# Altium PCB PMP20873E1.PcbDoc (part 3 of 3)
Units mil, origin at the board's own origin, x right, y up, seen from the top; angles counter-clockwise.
Board outline 7700 x 3300 mil, 6 copper layers (Layer 1 - Top Layer, Layer 2 - Inner Signal 1, Layer 3 - Inner Signal 2, Layer 4 - Inner Signal 3, Layer 5 - Inner Signal 4, Layer 6 - Bottom Layer), stack 64 mil thick; 258 components, 121 nets, 676 pads, 168 vias.
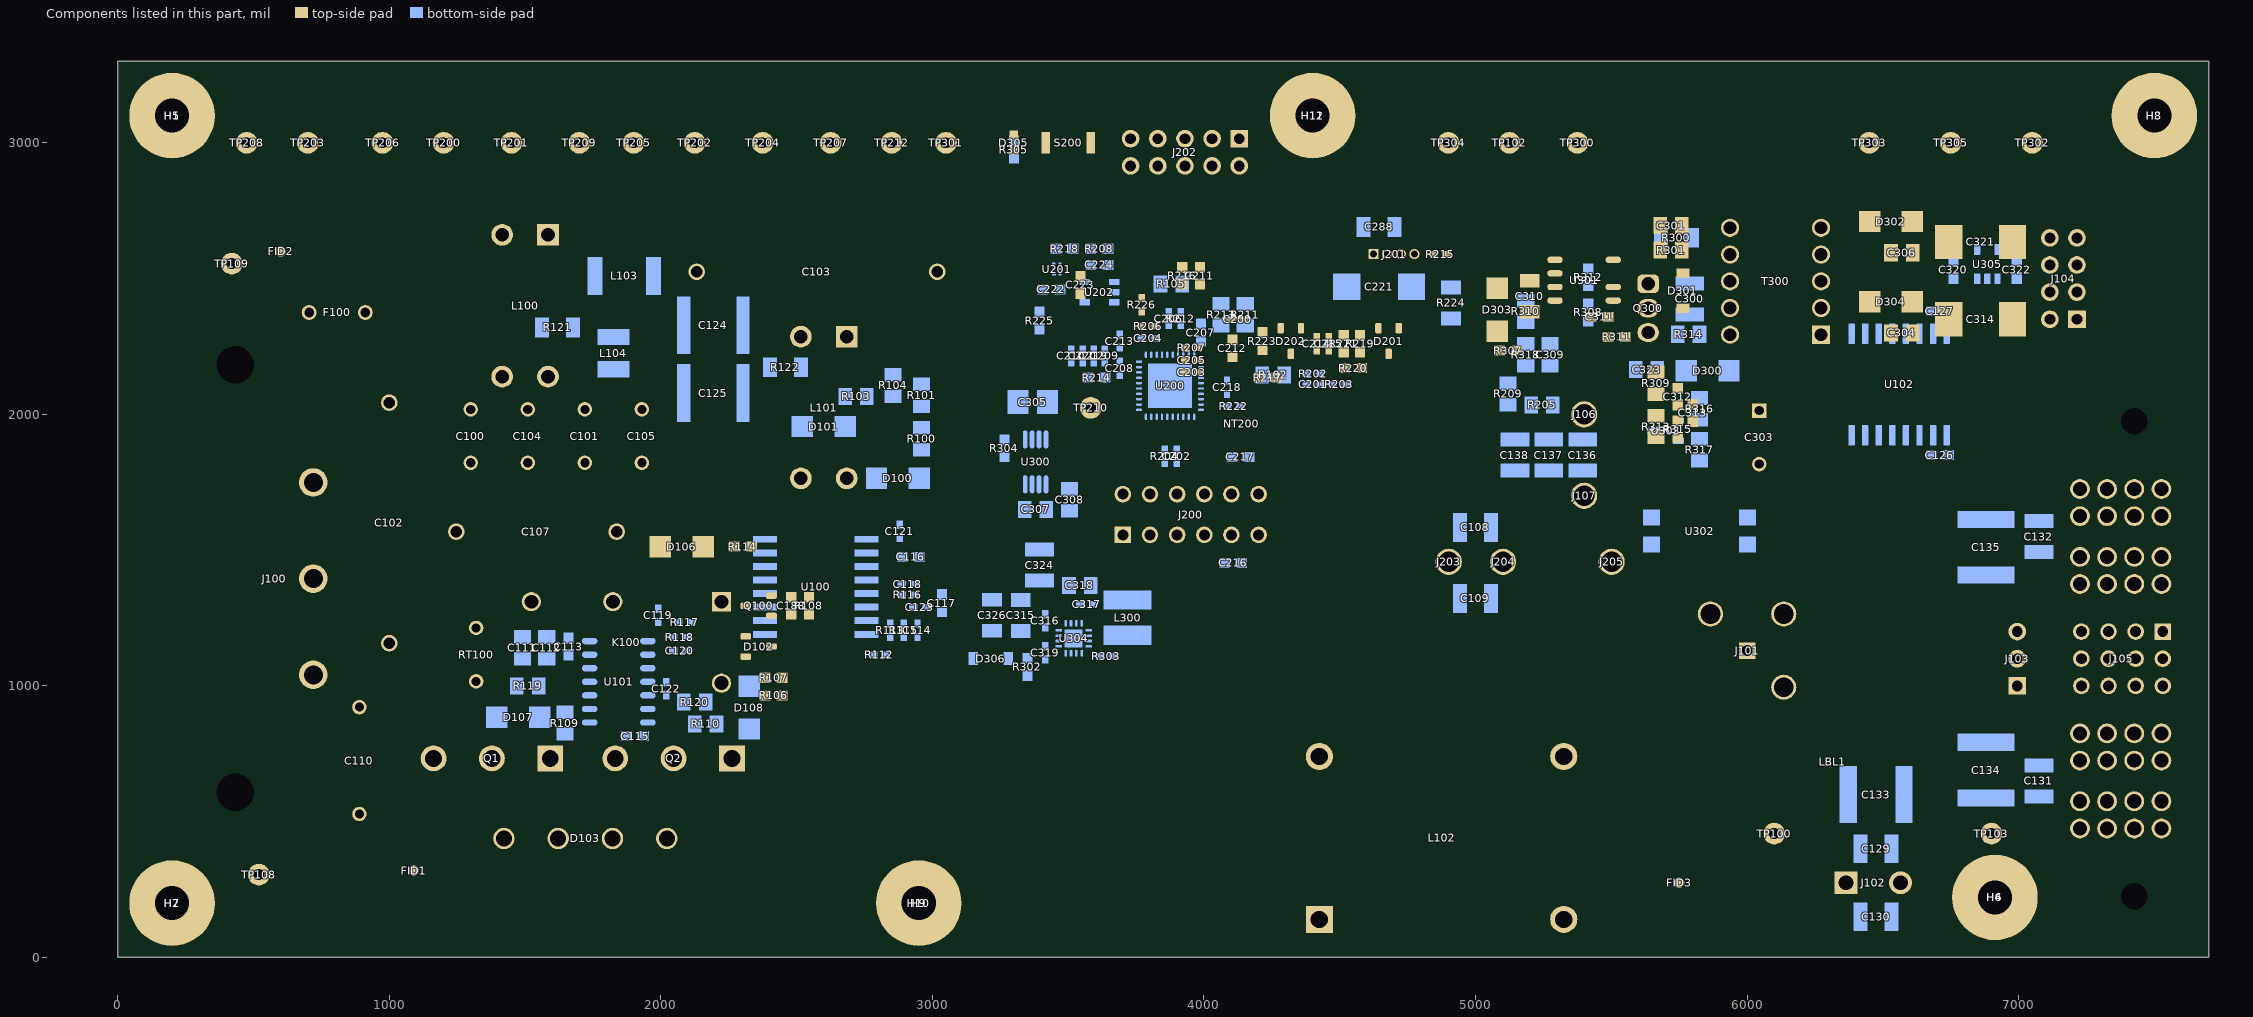
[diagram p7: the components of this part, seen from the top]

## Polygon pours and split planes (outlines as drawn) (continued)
5V on Layer 6 - Bottom Layer "5V_L06_P184" (solid, remove dead copper, pour order 184): 3310,1730 3310,1539 3419,1430 3539,1430 3546.48,1422.52 3545,1349 3574,1320 3574,1280 4100,1280 4100,1360 4100,1742.13 3950,1742.13 3950,1390 3930,1370 3680,1370 3660,1390 3660,1560 3550,1670 3440,1670 3360,1750 3330,1750
PGND_PFC on Layer 6 - Bottom Layer "PGND_PFC_L06_P182" (solid, remove dead copper, pour order 182): 3330,1115 3330,1010 3562,1010 3562,1131 3554,1139 3554,1208 3562,1216 3562,1313 3530,1345 3530,1418 3457,1418 3180,1418 3180,1245 3485,1245 3485,1135 3465,1115
12V on Layer 6 - Bottom Layer "12V_L06_P180" (solid, remove dead copper, pour order 180): 3455,1135 3230,1135 3184,1181 3184,1235 3435,1235 3445,1245 3495,1245 3495,1175
LLC_AGND on Layer 6 - Bottom Layer "Layer 6 - Bottom Layer-No Net 29" (solid, remove dead copper, pour order 103): 6235,2335 6400,2335 6400,2255 6235,2255
3V3 on Layer 6 - Bottom Layer "Layer 6 - Bottom Layer-No Net 27" (solid, remove dead copper, pour order 141): 3465,2570 3605,2570 3605,2475 3565,2435 3450,2435 3450,2555 3465,2570
NetC100_1 on Layer 6 - Bottom Layer "Layer 6 - Bottom Layer-No Net 26" (solid, remove dead copper, pour order 136): 1370,2095 1370,2219 1370,2375 1510,2515 1666,2515 1731,2580 1790,2580 1790,2435 1610,2435 1590,2415 1590,2280 1570,2260 1485,2175 1485,2095
NetL104_1 on Layer 6 - Bottom Layer "Layer 6 - Bottom Layer-No Net 25" (solid, remove dead copper, pour order 133): 1650,2360 1650,2270 1663,2257 1884,2257 1890,2263 1890,2335 1850,2375 1665,2375
NetC124_2 on Layer 6 - Bottom Layer "Layer 6 - Bottom Layer-No Net 24" (solid, remove dead copper, pour order 129): 2273.41,2438.41 2273.41,1968.41 2338.41,1968.41 2428.41,2058.41 2428.41,2215 2385,2215 2333.41,2266.59 2333.41,2438.41
NetC124_1 on Layer 6 - Bottom Layer "Layer 6 - Bottom Layer-No Net 23" (solid, remove dead copper, pour order 126): 2030,2585 1943.41,2585 1943.41,2153.41 2048.41,2048.41 2048.41,1968.41 2113.41,1968.41 2113.41,2431.59 2030,2515
PGND_PFC on Layer 6 - Bottom Layer "Layer 6 - Bottom Layer-No Net 13" (solid, remove dead copper, pour order 154): 5790,1855 5790,1770 5860,1770 5860,1855
12V on Layer 6 - Bottom Layer "Layer 6 - Bottom Layer-No Net 12" (solid, remove dead copper, pour order 153): 5890,2200 5890,2155 5936,2109 6041,2109 6105,2045 6105,1950 5970,1950 5885,2035 5697,2035 5645,2087 5645,2200
AGND on Layer 6 - Bottom Layer "Layer 6 - Bottom Layer-No Net 10" (solid, remove dead copper, pour order 152): 3385,1995 3505,1995 3505,2095 3385,2095
3V3 on Layer 6 - Bottom Layer "Layer 6 - Bottom Layer-No Net 2" (solid, remove dead copper, pour order 151): 3245,1885 3245,2150 3355,2150 3355,1970 3375,1950 3375,1885
HVBUS on Layer 6 - Bottom Layer "Layer 6 - Bottom Layer-No Net 7" (solid, remove dead copper, pour order 147): 5032,1638.27 5032,1253.27 5140,1253.27 5170,1283.27 5170,1403.27 5170,1608.27 5140,1638.27
PGND_PFC on Layer 6 - Bottom Layer "Layer 6 - Bottom Layer-No Net 6" (solid, remove dead copper, pour order 132): 4115,1750 4115,1185 4155,1145 4968,1145 4968,1580 5005,1617 5005,1790 4420,1790 4342,1868 4150,1868 4150,1785
3V3 on Layer 6 - Bottom Layer "Layer 6 - Bottom Layer-No Net 5" (solid, remove dead copper, pour order 150): 3585,2210 3650,2210 3650,2120 3620,2120 3620,2150 3595,2175 3585,2175
NetC210_1 on Layer 6 - Bottom Layer "Layer 6 - Bottom Layer-No Net 4" (solid, remove dead copper, pour order 149): 3555,2120 3500,2175 3500,2210 3570,2210 3570,2180 3590,2160 3590,2120
AGND on Layer 6 - Bottom Layer "Layer 6 - Bottom Layer-No Net 3" (solid, remove dead copper, pour order 148): 3490,2220 3490,2310 3710,2310 3710,2270 3670,2270 3650,2250 3650,2220
AGND on Layer 6 - Bottom Layer "Layer 6 - Bottom Layer-No Net 15" (solid, remove dead copper, pour order 166): 3390,1615 3390,1755 3440,1805 3540,1805 3540,1700 3480,1700 3450,1670 3450,1615
NetD107_2 on Layer 6 - Bottom Layer "Layer 6 - Bottom Layer-No Net 1" (solid, remove dead copper, pour order 90): 1505,930 1505,710 1530,685 1660,685 1685,710 1685,845 1675,855 1595,855 1595,930
NetD108_2 on Layer 6 - Bottom Layer "Layer 6 - Bottom Layer-No Net 16" (solid, remove dead copper, pour order 92): 2180,891 2365,891 2365,802 2315,752 2315,685 2210,685 2210,770 2180,800
+BRDG_P on Layer 6 - Bottom Layer "Layer 6 - Bottom Layer-No Net 19" (solid, remove dead copper, pour order 99): 1920,900 1980,900 2058,822 2150,822 2150,891 2134,891 2115,910 2115,926 2115,975 2055,975 2055,950 2035,930 1990,930 1920,930
-BRDG_N on Layer 6 - Bottom Layer "Layer 6 - Bottom Layer-No Net 20" (solid, remove dead copper, pour order 104): 2340,1353 2340,1185 2430,1095 2430,685 2365,620 2160,620 2125,655 2125,755 2095,785 2050,785 1906,641 1344,641 1220,765 1220,795 1100,795 1100,630 1100,100 2560,100 2915,455 2915,843 2625,1133 2625,1330 2602,1353
AC_N on Layer 6 - Bottom Layer "Layer 6 - Bottom Layer-No Net 21" (solid, remove dead copper, pour order 110): 1801,1751 1801,1529 2157,1529 2245,1441 2245,1377 2597,1377 2625,1405 2625,1770 2530,1865 1915,1865
AC_CUR_FAULT on Layer 6 - Bottom Layer "Layer 6 - Bottom Layer-No Net 22" (solid, remove dead copper, pour order 115): 2710,1355 2835,1355 2870,1390 2900,1390 2900,1320 2710,1320
NetD300_2 on Layer 6 - Bottom Layer "Layer 6 - Bottom Layer-No Net 28" (solid, remove dead copper, pour order 168): 5890,2325 5975,2325 5975,2120 5890,2120
PGND_PFC on Layer 6 - Bottom Layer "Layer 6 - Bottom Layer-No Net 33" (solid, remove dead copper, pour order 171): 5730,2395 5875,2395 5875,2265 5800,2265 5730,2335
12V on Layer 6 - Bottom Layer "Layer 6 - Bottom Layer-No Net 11" (solid, remove dead copper, pour order 98): 4865,2380 4865,2290 4955,2290 4955,2380
NetC221_1 on Layer 6 - Bottom Layer "Layer 6 - Bottom Layer-No Net 18" (solid, remove dead copper, pour order 102): 4930,2420 4670,2420 4655,2435 4655,2720 4665,2730 4780,2730 4950,2560 4950,2440
PGND_PFC on Layer 6 - Bottom Layer "Layer 6 - Bottom Layer-No Net 34" (solid, remove dead copper, pour order 107): 4470,2415 4470,2710 4490,2730 4620,2730 4635,2730 4645,2720 4645,2430 4630,2415
HVBUS on Layer 6 - Bottom Layer "Layer 6 - Bottom Layer-No Net 37" (solid, remove dead copper, pour order 118): 7541,1581 6774,1581 6765,1590 6765,1684 6856,1775 7545,1775 7565,1755 7565,1605
PGND_PFC on Layer 6 - Bottom Layer "Layer 6 - Bottom Layer-No Net 38" (solid, remove dead copper, pour order 122): 7547,1518 6858,1518 6770,1430 6770,1365 6805,1330 7545,1330 7565,1350 7565,1500
HVBUS on Layer 6 - Bottom Layer "Layer 6 - Bottom Layer-No Net 40" (solid, remove dead copper, pour order 125): 6765,619 7546,619 7565,600 7565,450 7545,430 7040,430 7005,465 7005,515 6970,550 6765,550
HVBUS on Layer 6 - Bottom Layer "Layer 6 - Bottom Layer-No Net 41" (solid, remove dead copper, pour order 128): 6445,95 6445,690 6410,725 6090,725 6040,675 6040,135 6080,95
PGND_PFC on Layer 6 - Bottom Layer "Layer 6 - Bottom Layer-No Net 42" (solid, remove dead copper, pour order 131): 6505,95 6505,725 6645,865 6765,865 7550,865 7565,850 7565,700 7546,681 6960,681 6731,681 6695,645 6695,535 6735,495 6930,495 6930,400 6920,390 6735,390 6735,140 6690,95
NetR205_1 on Layer 6 - Bottom Layer "Layer 6 - Bottom Layer-No Net 43" (solid, remove dead copper, pour order 138): 5085,2060 5230,2060 5230,2005 5085,2005
NetQ300_3 on Layer 6 - Bottom Layer "Layer 6 - Bottom Layer-No Net 44" (solid, remove dead copper, pour order 140): 5770,2330 5610,2330 5610,2280 5630,2260 5770,2260
HVBUS on Layer 6 - Bottom Layer "Layer 6 - Bottom Layer-No Net 45" (solid, remove dead copper, pour order 177): 5260,2070 5425,2070 5460,2035 5460,1890 5450,1880 5090,1880 5090,1935 5220,1935 5260,1975
PGND_PFC on Layer 6 - Bottom Layer "Layer 6 - Bottom Layer-No Net 47" (solid, remove dead copper, pour order 178): 5090,1820 5090,1710 5150,1650 5435,1650 5450,1665 5450,1820
NetF100_1 on Layer 5 - Inner Signal 4 "Layer 2 - Inner Signal 1-No Net" (solid, remove dead copper, pour order 96): 600,1675 600,2450 815,2450 815,1665 800,1650 625,1650
NetC103_2 on Layer 5 - Inner Signal 4 "Layer 2 - Inner Signal 1-No Net 3" (solid, remove dead copper, pour order 112): 1504,1980 1495,1980 1470,2005 1470,2035 1520,2085 1520,2357 1853,2690 3010,2690 3060,2640 3060,2154 2912,2006 2469,2006 2430,2045 2430,2305 2465,2340 2560,2340 2578,2322 2578,2182 2586,2174 2778,2174 2800,2196 2800,2375 2788,2387 2417,2387 2400,2370 2400,2120 1675,2120 1535,1980
EARTH on Layer 5 - Inner Signal 4 "Layer 2 - Inner Signal 1-No Net 9" (solid, remove dead copper, pour order 175): 1975,2075 1975,1925 1700,1925 1525,1750 1475,1700 1225,1700 1175,1650 1175,1600 1175,1100 950,875 855,875 825,905 825,1075 625,1275 625,1475 700,1550 725,1575 825,1575 925,1675 1150,1900 1325,1900 1525,1900 1700,2075
NetC101_1 on Layer 5 - Inner Signal 4 "Layer 5 - Inner Signal 4-No Net" (solid, remove dead copper, pour order 121): 2740,1872.5 1687.5,1872.5 1205,1390 1205,1165 1755,1165 2025,1435 2520,1435 2740,1655
PGND_PFC on Layer 5 - Inner Signal 4 "Layer 5 - Inner Signal 4-No Net 2" (solid, remove dead copper, pour order 139): 5975,2730 5975,2175 6095,2055 6095,1538 6375,1258 7557,1258 7590,1225 7590,945 7555.01,910.01 6245.01,910 6107.99,910.01 5780.02,910.02 5780.02,1043 6090,1043 6090,1220 5690,1220 5660,1250 5660,1345 5480,1525 5425,1525 4270,370 3015,370 2880,370 2585,75 840,75 800,115 800,490 920,610 1690,610 1700,620 1700,720 1875,895 1875,1200 2050,1375 2662,1375 2698,1339 2698,1125 2752,1071 3046,1071 3360,1385 4095,1385 4150,1440 4150,2045 4180,2075 4795,2075 4810,2090 4810,2380 4780,2410 4510,2410 4475,2445 4475,2695 4510,2730 4799,2730 4930,2730 5490,2730 5550,2670 5695,2670 5755,2730
AGND on Layer 5 - Inner Signal 4 "Layer 5 - Inner Signal 4- AGND" (solid, pour order 144): 3036.2,1085 3716.2,1765 3991.2,1765 4130,1903.8 4130,2068.8 4156.2,2095 4396.2,2095 4725,2095 4750,2120 4750,2355 4730,2375 4494.92,2375 4449.11,2421.05 4450.69,2730 3145,2730 3145,1715 3059,1629 2779,1629 2715,1565 2715,1125 2755,1085
AGND on Layer 5 - Inner Signal 4 "Layer 5 - Inner Signal 4-No Net 3" (solid, remove dead copper, pour order 169): 400,3045 400,2835 430,2805 2970,2805 3150,2625 4190,2625 4190,3065 4180,3075 430,3075
NetC102_1 on Layer 5 - Inner Signal 4 "Layer 2 - Inner Signal 1-No Net 2" (solid, remove dead copper, pour order 101): 875,2000 875,2575 1025,2725 1462,2725 1462,2412 1050,2000
NetC101_1 on Layer 2 - Inner Signal 1 "Layer 2 - Inner Signal 1-No Net 6" (solid, remove dead copper, pour order 157): 1700,1875 1795,1875 1909,1761 1996,1761 2110,1875 2705,1875 2750,1830 2750,1680 2670,1600 2190,1600 2135,1655 1695,1655 1650,1700 1650,1825
AC_L on Layer 2 - Inner Signal 1 "Layer 2 - Inner Signal 1-No Net 4" (solid, remove dead copper, pour order 94): 700,565 700,205 830,75 2585,75 2835,325 3075,325 3325,75 4490,75 4525,110 4525,515 4115,925 2625,925 1935,1615 1750,1615 1235,1615 1205,1585 1205,1070
NetC103_2 on Layer 2 - Inner Signal 1 "Layer 2 - Inner Signal 1-No Net 3" (solid, remove dead copper, pour order 111): 1504,1980 1495,1980 1470,2005 1470,2035 1520,2085 1520,2357 1853,2690 3010,2690 3060,2640 3060,2154 2912,2006 2469,2006 2430,2045 2430,2305 2465,2340 2560,2340 2578,2322 2578,2182 2586,2174 2778,2174 2800,2196 2800,2375 2788,2387 2417,2387 2400,2370 2400,2120 2380,2100 1655,2100 1535,1980
NetC102_1 on Layer 2 - Inner Signal 1 "Layer 2 - Inner Signal 1-No Net 2" (solid, remove dead copper, pour order 100): 875,2000 875,2575 1025,2725 1428,2725 1463,2690 1463,2414 1049,2000
NetF100_1 on Layer 2 - Inner Signal 1 "Layer 2 - Inner Signal 1-No Net" (solid, remove dead copper, pour order 97): 600,1700 600,2450 815,2450 815,1690 775,1650 650,1650
LLC_AGND on Layer 2 - Inner Signal 1 "Layer 2 - Inner Signal 1-No Net 1" (solid, remove dead copper, pour order 155): 6260,2630 6650,2630 6685,2665 6685,2750 6710,2775 7255,2775 7285,2745 7285,2275 7265,2255 6240,2255 6235,2260 6235,2325 6245,2335 6655,2335 6685,2365 6685,2515 6650,2550 6255,2550 6235,2570 6235,2605
PGND_PFC on Layer 2 - Inner Signal 1 "Layer 6 - Bottom Layer-No Net" (solid, pour order 142): 4540,2040 4675,2175 5975,2175 6190,1960 6960,1960 7385,1535 7600,1535 7600,670 7160,670 7110,620 7110,490 7040,420 6790,420 6730,360 6730,200 6680,150 6520,150 6470,200 6470,380 6445,405 6310,405 6130,585 5781.5,933.51 5781.5,1033.46 6094.49,1033.46 6094.49,1222.44 5827.56,1222.44 5550,1500 5050,1500 4925,1375 4790,1375 4540,1625 4540,1797.5 4472.5,1865 4472.5,1972.5
3V3 on Layer 2 - Inner Signal 1 "Layer 2 - Inner Signal 1-3v3" (solid, remove dead copper, pour order 145): 4830,2355 4475,2000 3935,2000 3020,1085 2810,1085 2760,1135 2760,1590 2825,1655 3090,1655 3150,1715 3150,2655 4115,2655 4785,2655 4830,2610
3V3 on Layer 2 - Inner Signal 1 "Layer 2 - Inner Signal 1-No Net 5" (solid, remove dead copper, pour order 170): 4255,2640 4190,2705 4190,2895 4190,3060 4175,3075 3200,3075 3015,3075 2980,3040 2980,2825 3205,2600 4295,2600
EARTH on Layer 2 - Inner Signal 1 "Layer 2 - Inner Signal 1-No Net 9" (solid, remove dead copper, pour order 174): 1975,2030 1975,1955 1945,1925 1700,1925 1525,1750 1475,1700 1225,1700 1175,1650 1175,1600 1175,1100 950,875 855,875 825,905 825,1075 625,1275 625,1475 700,1550 725,1575 825,1575 925,1675 1150,1900 1325,1900 1525,1900 1670,2045 1960,2045
NetC100_1 on Layer 4 - Inner Signal 3 "Layer 3 - Inner Signal 2-No Net 1" (solid, remove dead copper, pour order 106): 1250,2086 1615,2451 1697,2451 1739,2493 1739,2575 2740,2575 2740,2090 1390,2090 1350,2050 1350,1980 1250,1980
NetC102_2 on Layer 4 - Inner Signal 3 "Layer 4 - Inner Signal 3-No Net 1" (solid, remove dead copper, pour order 117): 1640,2710 1640,2610 1640,2530 1560,2530 1120,2090 1120,980 590,980 590,2310 990,2710
NetC101_1 on Layer 4 - Inner Signal 3 "Layer 5 - Inner Signal 4-No Net" (solid, remove dead copper, pour order 120): 2740,1865 1695,1865 1260,1430 1260,970 1770,970 2060,1260 2060,1355 2175,1470 2595,1470 2740,1615
EARTH on Layer 4 - Inner Signal 3 "Layer 3 - Inner Signal 2-No Net 2" (solid, remove dead copper, pour order 173): 1980,2065 1980,1910 1695,1910 1585,1800 1555,1770 1215,1770 1215,1910 1545,1910 1695,2060
HVBUS on Layer 4 - Inner Signal 3 "Layer 4 - Inner Signal 3-No Net" (solid, remove dead copper, pour order 137): 1192,169 1192,682 1290,780 1335,780 1465,780 1465,645 1485,625 2370,625 2790,1045 3805.83,1045 4935.83,2175 5320,2175 5425,2175 5495,2105 5495,1975 5725,1745 6800,1745 6830,1775 7560,1775 7600,1735 7600,1610 7560,1570 7185,1570 7140,1525 7140,665 7180,625 7565,625 7600,590 7600,455 7565,420 6830,420 6830,305 6675,150 6140,150 6080,150 5995,235 5995,735 6230,970 6230,1315 6200,1345 5660,1345 5505,1500 5400,1500 4435,535 4275,535 4105,365 2875,365 2583,73 1288,73
NetF100_1 on Layer 1 - Top Layer "Layer 2 - Inner Signal 1-No Net" (solid, remove dead copper, pour order 95): 600,1675 600,2450 815,2450 815,1665 800,1650 625,1650
ACN_SENSE on Layer 1 - Top Layer "Layer 1 - Top Layer-No Net 5" (solid, remove dead copper, pour order 91): 4005,2500 3885,2500 3885,2450 3935,2400 3965,2400 4005,2440
7VLLC on Layer 1 - Top Layer "Layer 1 - Top Layer-No Net 9" (solid, remove dead copper, pour order 164): 6565,2460 6565,2375 6580,2360 6580,2265 6795,2265 6795,2415 6840,2460 6770,2460
10VLLC on Layer 1 - Top Layer "Layer 1 - Top Layer-No Net 8" (solid, remove dead copper, pour order 162): 6570,2755 6570,2640 6580,2630 6580,2560 6795,2560 6795,2755
LLC_AGND on Layer 1 - Top Layer "Layer 1 - Top Layer-No Net 7" (solid, remove dead copper, pour order 160): 6555,2335 6235,2335 6235,2255 6555,2255
LLC_AGND on Layer 1 - Top Layer "Layer 1 - Top Layer-No Net 7" (solid, remove dead copper, pour order 161): 6555,2630 6235,2630 6235,2550 6555,2550
LLC_AGND on Layer 1 - Top Layer "Layer 1 - Top Layer-No Net 6" (solid, remove dead copper, pour order 158): 6920,2415 6920,2280 7065,2280 7065,2415
LLC_AGND on Layer 1 - Top Layer "Layer 1 - Top Layer-No Net 6" (solid, remove dead copper, pour order 159): 6920,2705 6920,2565 7065,2565 7065,2705
NetC301_2 on Layer 1 - Top Layer "Layer 1 - Top Layer-No Net 3" (solid, remove dead copper, pour order 146): 5705,2730 5610,2730 5610,2570 5705,2570
SWNODE on Layer 1 - Top Layer "Layer 1 - Top Layer-No Net 1" (solid, remove dead copper, pour order 134): 5235,645 5235,1310 5440.75,1515.75 5534.25,1515.75 5575,1475 5590,1460 5590,1110 5590,645
AGND on Layer 1 - Top Layer "Layer 1 - Top Layer-No Net" (solid, remove dead copper, pour order 124): 3950,2215 3950,2145 3960,2135 3960,2010 3790,2010 3790,2155 3820,2185 3825,2190 3855,2190 3860,2190 3885,2215
NetD301_2 on Layer 1 - Top Layer "Layer 1 - Top Layer-No Net 2" (solid, remove dead copper, pour order 143): 5610,2425 5975,2425 5975,2355 5610,2355
NetC102_2 on Layer 1 - Top Layer "Layer 1 - Top Layer-No Net 4" (solid, remove dead copper, pour order 163): 600,1025 600,1175 650,1225 1025,1225 1075,1175 1075,1075 1025,1025 850,1025 800,975 650,975
12V on Layer 1 - Top Layer "12V_L01_P192" (solid, remove dead copper, pour order 192): 2425,1050 2490,1050 2540,1000 2485,945 2425,945
NetD102_2 on Layer 1 - Top Layer "NETD102_2_L01_P194" (solid, remove dead copper, pour order 194): 2405,945 2215,945 2175,985 2175,1035 2260,1120 2355,1120 2405,1070
NetD102_1 on Layer 1 - Top Layer "NETD102_1_L01_P196" (solid, remove dead copper, pour order 196): 2185,1350 2310,1350 2335,1325 2335,1165 2285,1165 2185,1265
AC_L on Layer 3 - Inner Signal 2 "Layer 2 - Inner Signal 1-No Net 4" (solid, remove dead copper, pour order 93): 700,565 700,200 825,75 1350,75 2585,75 2835,325 3075,325 3325,75 4525,75 4525,515 4115,925 2625,925 1935,1615 1235,1615 1205,1585 1205,1070
EARTH on Layer 3 - Inner Signal 2 "Layer 3 - Inner Signal 2-No Net 2" (solid, remove dead copper, pour order 172): 1980,2044.74 1980,1970 1960,1950 1735,1950 1585,1800 1555,1770 1240,1770 1215,1795 1215,1875 1250,1910 1545,1910 1674.37,2039.37
12V on Layer 3 - Inner Signal 2 "Layer 3 - Inner Signal 2-No Net" (solid, remove dead copper, pour order 123): 3210,2650 5480,2650 5530,2600 5530,2380 5650,2260 5870,2260 6170,1960 6345,1960 6440,1865 6440,1080 6425,1065 6360,1065 6335,1090 6335,1210 6190,1355 5670,1355 4825,2200 4175,2200 4140,2165 4140,1420 3855,1135 3290,1135 3150,1275 3150,2590
NetC100_1 on Layer 3 - Inner Signal 2 "Layer 3 - Inner Signal 2-No Net 1" (solid, remove dead copper, pour order 105): 1250,2086 1615,2451 1697,2451 1739,2493 1739,2549 1765,2575 2695,2575 2740,2530 2740,2130 2700,2090 1760,2090 1620,2230 1570,2230 1430,2090 1390,2090 1350,2050 1350,2000 1330,1980 1270,1980 1250,2000
NetC102_2 on Layer 3 - Inner Signal 2 "Layer 4 - Inner Signal 3-No Net 1" (solid, remove dead copper, pour order 116): 1640,2690 1640,2610 1640,2550 1620,2530 1560,2530 1120,2090 1120,1040 1060,980 640,980 590,1030 590,2310 990,2710 1620,2710
NetC101_1 on Layer 3 - Inner Signal 2 "Layer 2 - Inner Signal 1-No Net 6" (solid, remove dead copper, pour order 156): 1700,1875 1795,1875 1909,1761 1996,1761 2050,1815 2750,1815 2750,1680 2670,1600 2190,1600 2135,1655 1695,1655 1650,1700 1650,1825

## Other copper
Layer 1 - Top Layer:
  region net AGND: 4005,2518 3885.5,2518 3885.5,2620 4005,2620
Layer 2 - Inner Signal 1:
  pour cut-out: 1960,1257.28 1960,1435 1895,1500 1895,1615 2145,1615 2145,1102.28 2115,1102.28
  pour cut-out: 1365,645 1365,815 1390,840 1515,840 1515,625 1385,625
  pour cut-out: 1762.79,663.79 1762.79,927.32 1867.31,1031.84 1898.16,1031.84 2089.5,840.5 2170,840.5 2170,625 1801.59,625
  pour cut-out: 2181.21,979.8 2181.21,1295 2388.41,1295 2640,1043.41 2640,925 2236,925
  pour cut-out: 1420,340 1420,535 1620,535 1620,340
Layer 3 - Inner Signal 2:
  pour cut-out: 1420,337.5 1420,532.5 1620,532.5 1620,337.5
  pour cut-out: 1762.79,663.79 1762.79,927.32 1867.31,1031.84 1898.16,1031.84 2089.5,840.5 2170,840.5 2170,625 1801.59,625
  pour cut-out: 2181.21,933.79 2181.21,1295 2388.41,1295 2640,1043.41 2640,925 2190,925
  pour cut-out: 1365,645 1365,815 1390,840 1515,840 1515,625 1385,625
  pour cut-out: 1960,1257.28 1960,1435 1895,1500 1895,1615 2145,1615 2145,1102.28 2115,1102.28
Layer 4 - Inner Signal 3:
  pour cut-out: 1418,339.5 1418,534.5 1815,534.5 1815,339.5
  pour cut-out: 2420,1760 2420,1905 2610,1905 2755,1905 2755,1825 2610,1825 2610,1760
Layer 5 - Inner Signal 4:
  pour cut-out: 1555,535 2095,535 2120,510 2120,370 2090,340 1555,340 1525,370 1525,505
  pour cut-out: 2420,1760 2420,1905 2610,1905 2755,1905 2755,1825 2610,1825 2610,1760
Layer 6 - Bottom Layer:
  pour cut-out: 1825,340 1825,535 2025,535 2025,340

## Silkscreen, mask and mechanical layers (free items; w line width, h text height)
Top Overlay:
  region: 6961,1948 6661,1948 6661,1848 6961,1848
  lines w5: 5400,1550 3200,1550 3200,2800 5400,2800
  lines w8: 4650,1950 4650,1970
  lines w10: 3601.3,1656.05 3701.3,1656.05 ; 3601.3,1657.05 3601.3,1007.05 3701.3,1007.05 ; 5551.3,1007.05 5651.3,1007.05 5651.3,1657.05 5551.3,1657.05
  text "Enable" at 3170,3095 h40
  text "Restart" at 3425,3090 h40
  text "PGND / FAN 12V / FB / CONTROL" at 4800,2825 h30 r90
  text "Iso" at 7425,2725 h40
  text "L" at 400,2650 h40
  text "10V" at 7340,2625 h40
  text "AGND" at 7465,2625 h40
  text "7V" at 7365,2525 h40
  text "SCI TX" at 7465,2525 h40
  text "3.3V" at 7290,2425 h40
  text "UVLO" at 7465,2425 h40
  text "AGND" at 7290,2325 h40
  text "SCI RX" at 7465,2325 h40
  text ".PRJ_Number" at 6485,1990 h60
  text ".PCB_Rev" at 6481,1868.01 h60
  text "-" at 6591,1868.01 h60
  text "Danger" at 6240,1490 h40
  text "Caution" at 6720,1490 h40
  text "Switch" at 5815,1435 h40
  text "5V" at 4025,1415.32 h40 r90
  text "High Voltage" at 6140,1415 h40
  text "Hot Surface" at 6645,1415 h40
  text "12V" at 4125,1382 h40 r90
  text "Node" at 5860,1375 h40
  text "AGND" at 4220,1335.34 h40 r90
  text "VDC" at 5115,1257.03 h40 r90
  text "-" at 5750,1239.84 h40
  text "-" at 6229.84,1239.84 h40
  text "HS Gate" at 3690,1222.05 h40 r90
  text "LS Gate" at 3815,1222.05 h40 r90
  text "PGND" at 4920,1217.05 h40 r90
  text "SW" at 5520,1188.75 h40 r90
  text "12V" at 6811.02,1181.1 h40
  text "GaN Fault" at 3915,1155.4 h40 r90
  text "+" at 6060,1110 h40
  text "PGND" at 6771.65,1082.68 h40
  text "-" at 6229.84,980 h40
  text "PGND_pfc" at 6621.72,980 h40
  text "LMG34XX-PFC-EVM" at 5890,695 h60
  text "For TI demo use only" at 1345,220 h60
  text "+ HV OUT -" at 6280,30 h40
  text "VSW2" at 9498,-2758 h40
M1 Board Outline:
  lines w5: 0,300 0,3300 7700,3300 7700,300 0,300 ; 5581,2340 5581,2350 5691,2350 5691,2340 5581,2340 ; 5581,2429.76 5691,2429.76 5691,2439.76 5581,2439.76 5581,2429.76 ; 5888,2330 5888,2355 5988,2355 5988,2330 5888,2330 ; 5888,2625.28 5988,2625.28 5988,2650.28 5888,2650.28 5888,2625.28
  text ".Layer_Name" at 577,-1958.49 h60
M2 Board Dimensions:
  rectangle: -0.5,-1385.5 124.5,-1260.5
  rectangle: 124.5,-1510.5 499.5,-1385.5
  lines w7: -0.5,-1385.5 999.5,-1385.5 ; 124.5,-1510.5 124.5,-1260.5 ; 249.5,-1510.5 249.5,-1260.5 ; 499.5,-1510.5 499.5,-1260.5 ; 749.5,-1510.5 749.5,-1260.5 ; -0.5,-1510.5 999.5,-1510.5 999.5,-1260.5 -0.5,-1260.5 -0.5,-1510.5
  lines w10: -0.5,-1575.5 -0.5,-1555.5 ; 59.5,-1585.5 -0.5,-1565.5 ; 59.5,-1545.5 -0.5,-1565.5 ; 223.58,-1565.5 -0.5,-1565.5 ; 775.42,-1565.5 999.5,-1565.5 ; 939.5,-1585.5 999.5,-1565.5 ; 939.5,-1545.5 999.5,-1565.5 ; 999.5,-1575.5 999.5,-1555.5
  text "1000 (mil)" at 233.58,-1601.49 h60
  text ".Layer_Name" at 577,-1958.49 h60
M3 3D STEP Top:
  text ".Layer_Name" at 577,-1958.49 h60
M4 3D STEP Bottom:
  text ".Layer_Name" at 577,-1958.49 h60
M5 Assembly Top:
  lines w10: -292,-2030.17 6308,-2030.17 ; -292,-1826.83 6310,-1826.83 ; -292,-1623.5 -292,-2233.5 3713,-2233.5 6310,-2233.5 6310,-1623.5 -291.5,-1623.5 -291.5,-2233.5 1284,-2233.5 ; 2173,-2233.5 2173,-1623.5 ; 3440,-1826.83 3440,-1623.5 ; 4280,-1826.83 4280,-1623.5 ; 4902,-2240 4902,-2037.17
  text "COMPONENTS MARKED 'DNP' SHOULD NOT BE POPULATED." at 1153.5,-1418.5 h60
  text "ASSEMBLY VARIANT:" at 1153,-1534 h60
  text ".VariantName" at 2189,-1534 h60
  text "PCB VIEWED FROM TOP SIDE" at -228.5,-1755.67 h60
  text "BOARD #:" at 2248,-1755.67 h60
  text ".PRJ_Number" at 2793.5,-1755.67 h60
  text "REV:" at 3638,-1755.67 h60
  text ".PCB_Rev" at 3929.5,-1755.67 h60
  text "SVN REV:" at 4476,-1755.67 h60
  text ".VersionControl_RevNumber" at 4982,-1755.67 h60
  text "IGNORE ->" at -228.5,-1958.49 h60
  text "PLOT NAME =" at -228.5,-2164.34 h60
  text ".plot_File_Name" at 577,-2164.34 h60
  text "GENERATED    :" at 2250,-2164.34 h60
  text ".Print_Date" at 3119.5,-2164.34 h60
  text ".Print_Time" at 3848.5,-2164.34 h60
  text "TEXAS INSTRUMENTS" at 5113,-2164.34 h60
M6 Assembly Bottom:
  lines w10: -292.5,-1827.33 6309.5,-1827.33 ; -290.5,-2030.67 6309.5,-2030.67 ; 1115.5,-2240.5 1115.5,-2037.67 ; 1737.5,-1827.33 1737.5,-1624 ; 2577.5,-1827.33 2577.5,-1624 ; 3844.5,-2234 3844.5,-1624 ; 4733.5,-2234 6309,-2234 6309,-1624 -292.5,-1624 -292.5,-2234 2304.5,-2234 6309.5,-2234 6309.5,-1624
  text "COMPONENTS MARKED 'DNP' SHOULD NOT BE POPULATED." at 6102,-1418 h60
  text ".VariantName" at 5058,-1534 h60
  text "ASSEMBLY VARIANT:" at 6097,-1534 h60
  text ".VersionControl_RevNumber" at 1035.5,-1756.17 h60
  text "SVN REV:" at 1541.5,-1756.17 h60
  text ".PCB_Rev" at 2088,-1756.17 h60
  text "REV:" at 2379.5,-1756.17 h60
  text ".PRJ_Number" at 3224,-1756.17 h60
  text "BOARD #:" at 3769.5,-1756.17 h60
  text "PCB VIEWED FROM BOTTOM SIDE" at 6246,-1756.17 h60
  text "IGNORE ->" at 2547.85,-1958.49 h60
  text "TEXAS INSTRUMENTS" at 904.5,-2164.84 h60
  text ".Print_Time" at 2169,-2164.84 h60
  text ".Print_Date" at 2898,-2164.84 h60
  text "GENERATED    :" at 3767.5,-2164.84 h60
  text ".plot_File_Name" at 5440.5,-2164.84 h60
  text "PLOT NAME =" at 6246,-2164.84 h60
M9 Title Sheet:
  drawing of 55 lines, arcs and shapes, not listed
  text "1" at 739.84,6936.5 h70
  text "2" at 3235.5,6936.5 h70
  text "3" at 5724.84,6936.5 h70
  text "6" at 13235.5,6936.5 h70
  text "A" at -416.5,5793.5 h70
  text "A" at 14383.5,5793.5 h70
  text "B" at -416.5,3413.5 h70
  text "B" at 14383.5,3413.5 h70
  text "C" at -416.5,1038.5 h70
  text "C" at 14383.5,1038.5 h70
  text "PROJECT TITLE:" at 11343.5,-822.5 h45
  text ".PRJ_Title" at 11393.5,-955.83 h70
  text "DESIGNED FOR:" at 11343.5,-1123.5 h45
  text ".PRJ_Customer" at 11393.5,-1263.5 h70
  text "D" at -416.5,-1331.5 h70
  text "D" at 14383.5,-1331.5 h70
  text "FILE NAME:" at 11343.5,-1423.5 h45
  text ".PCB_File_Name_No_Path" at 11393.5,-1543.5 h70
  text "Texas Instruments (TI) and/or its licensors do not warrant the accuracy or completeness of this specification" at 6374,-1705.34 h45
  text "ENGINEER:" at 11343.5,-1713.5 h45
  text "LAYOUT BY:" at 12848.5,-1713.5 h45
  text "or any information contained therein. TI and/or its licensors do not warrant that this design will meet" at 6329.01,-1818 h45
  text ".PRJ_Engineer" at 11393.5,-1868.49 h70
  text ".PCB_Layout" at 12899,-1868.49 h70
  text "the specifications, will be suitable for your application or fit for any particular purpose, or will operate in" at 6329.01,-1930.67 h45
  text ".Layer_Name" at 577,-1958.49 h60
  text "ALTIUM DESIGNER VERSION:" at 12848.5,-2023.5 h45
  text "an implementation. TI and/or its licensors do not warrant that the design is production worthy. You should" at 6329.01,-2043.33 h45
  text "completely validate and test your design implementation to confirm the system functionality for your application." at 6374,-2156 h45
  text ".print_Scale" at 11393.5,-2156.83 h70
  text ".Application_BuildNumber" at 12899,-2156.83 h70
  text "1" at 739.84,-2363.5 h70
  text "2" at 3235.5,-2363.5 h70
  text "3" at 5724.84,-2363.5 h70
  text "4" at 8231.51,-2363.5 h70
  text "5" at 10730.5,-2363.5 h70
  text "6" at 13235.5,-2363.5 h70
M10 Fab Notes:
  drawing of 200 lines, arcs and shapes, not listed
  text "DESIGN INFORMATION" at 12381.02,5710 h60
  text "(REFER ALSO ARRAY/PANEL PROFILING INFORMATION)" at 12019.46,5548.29 h60
  text "BOARD SIZE" at 11333.46,5544 h60
  text "3300MIL" at 11795.78,5416.18 h60
  text "X" at 12301.46,5416.18 h60
  text "7700MIL" at 12532.78,5416.18 h60
  text "Number of Layers :" at 11736.46,5219 h60
  text "6" at 12831.27,5209 h60
  text "MIN. TRACK WIDTH:" at 11736.46,5080 h60
  text "7" at 12832.7,5080 h60
  text "MIL" at 12987.46,5080 h60
  text "MIN. CLEARANCE:" at 11736.46,4948 h60
  text "7" at 12832.7,4948 h60
  text "MIL" at 12987.46,4948 h60
  text "MIN. VIA PAD SIZE:" at 11736.46,4816 h60
  text "20" at 12802.71,4816 h60
  text "MIL" at 12987.46,4816 h60
  text "0.05mm (2MIL)" at 12431.46,4674.29 h60
  text "MINIMUM ANNULAR RING" at 11407.23,4670 h60
  text "EXTERNAL" at 13139.46,4670 h60
  text "PER" at 11607.23,4552 h60
  text "IPC-D-275 CLASS 2 LEVEL C" at 11827.23,4552 h60
  text "MIL, HOLES" at 13315.46,4439.71 h60
  text "+/-" at 12923,4439 h60
  text "+/-" at 13777,4439 h60
  text "REGISTRATION TOLERANCES:" at 11407.23,4434 h60
  text "METAL" at 12607,4434 h60
  text "5" at 13183.2,4434 h60
  text "3" at 14016.2,4434 h60
  text "MIL" at 14132.46,4434 h60
  text "MATERIAL:" at 11332.46,4224.54 h60
  text "FR-4 High Tg" at 12318.9,4084.21 h60
  text "FR-408" at 11753.46,4075.64 h60
  text "X" at 12165.46,4075.64 h60
  text "OTHER" at 13241.46,4075.64 h60
  text "62 MIL (1.6mm) +/-10%" at 12073.56,3912.92 h60
  text "THICKNESS:" at 11407.23,3908.64 h60
  text "X" at 11945.4,3908.64 h60
  text "OTHER" at 13358.46,3908.64 h60
  text "TOLERANCE:" at 11407.23,3750.64 h60
  text "X" at 12246.53,3750.64 h60
  text "ANSI IPC-6012 TYPE 3 CLASS 2" at 12433.48,3750.64 h60
  text "OTHER +/-" at 12433.46,3594.64 h60
  text "BOW & TWIST:" at 11407.23,3437.64 h60
  text "X" at 12246.53,3437.64 h60
  text "ANSI IPC-6012 TYPE 3 CLASS 2" at 12433.48,3437.64 h60
  text "OTHER +/-" at 12433.46,3279.13 h60
  text "COPPER THICKNESS (FINISHED):" at 11332.46,3143.64 h60
  text "1.4MIL (1oz)" at 12212.46,2990.92 h60
  text "2MIL (1.4oz)" at 12979.46,2990.92 h60
  text "2.8MIL (2oz)" at 13706.46,2990.92 h60
  text "OUTER:" at 11689.46,2986.64 h60
  text "X" at 12084,2986 h60
  text "1.4MIL (1oz)" at 12212.46,2833.92 h60
  text "2.8MIL (2oz)" at 12979.46,2833.92 h60
  text "N/A" at 13706,2834.29 h60
  text "INNER SIGNAL:" at 11400.38,2829.64 h60
  text "X" at 12855,2825 h60
  text "DRILLING:" at 11332.46,2690.64 h60
  text "REFERENCE:" at 11407.23,2573.64 h60
  text "X" at 12055.46,2573.64 h60
  text "AS SHOWN" at 12242.46,2573.64 h60
  text "X" at 12956.46,2573.64 h60
  text "NC_DRILL FILES" at 13093.46,2573.64 h60
  text "PTH MIN COPPER THICKNESS:" at 11407.23,2415.64 h60
  text "X" at 12757.46,2415.64 h60
  text "1MIL" at 12894.46,2415.64 h60
  text "OTHER" at 13391.46,2415.64 h60
  text "BOARD FINISH:" at 11332.46,2256.64 h60
  text "X" at 12436.46,2138.64 h60
  text "TOP" at 12562.46,2138.64 h60
  text "X" at 12946.46,2138.64 h60
  text "BOTTOM" at 13073.46,2138.64 h60
  text "SILKSCREEN:" at 11500,2100 h60
  text "SILKSCREEN COLOR:" at 11487.68,1971.64 h60
  text "X" at 12435.42,1971.64 h60
  text "WHITE" at 12562.46,1971.64 h60
  text "OTHER" at 13073.46,1971.64 h60
  text "SOLDER RESIST COLOR:" at 11487.68,1801.64 h60
  text "GREEN" at 12182.46,1642.44 h60
  text "BLUE" at 12773.46,1642.44 h60
  text "OTHER" at 13311.46,1642.44 h60
  text "IMMERSION GOLD (ENIG)" at 12393.46,1453.92 h60
  text "ENEPIG" at 13731,1450.64 h60
  text "SURFACE FINISH:" at 11332.46,1449.64 h60
  text "X" at 12206.51,1449.64 h60
  text "IMM. TIN/SILVER OR EQUIV" at 11662,1292.64 h60
  text "OTHER" at 13093.46,1292.64 h60
  text "CUT AND TRIM PER MECH LAYER 1" at 12393.46,1109.35 h60
  text "N.C. ROUTE" at 12393.46,957.64 h60
  text "X" at 13072.46,957.64 h60
  text "V. SCORE" at 13259.46,957.64 h60
  text "CERTIFICATION:" at 11332.46,820.64 h60
  text "MATERIALS AND WORKMANSHIP FOR ALL PCBS" at 12057.46,820.64 h60
  text "TO MEET OR EXCEED THE REQUIREMENTS OF:" at 12057.46,722.64 h60
  text "ANSI IPC-A-600F CLASS ->" at 11822.96,586.13 h60
  text "X" at 13462.02,586.13 h60
  text "2" at 13580.96,586.14 h60
  text "1" at 13265.96,584.64 h60
  text "3" at 13934.96,584.64 h60
  text "UL 94V-0" at 11822.96,426.64 h60
  text "X" at 12498.02,426.64 h60
  text "RoHS" at 12634.96,426.64 h60
  text "OTHER" at 13279.36,426.64 h60
  text "PER ORDER" at 13676.42,426.64 h60
  text "ADDITIONAL REQUIREMENTS:" at 11332.46,285.64 h60
  text "MICROSECTION:" at 11407.23,170.64 h60
  text "YES" at 12312.96,170.64 h60
  text "REQUIRED" at 13174.46,14.49 h60
  text "BARE BOARD ELEC. TEST:" at 11407.23,11.64 h60
  text "NONE" at 12712.96,11.64 h60
  text "X" at 13047.46,11.64 h60
  text "PER ORDER" at 13766.46,11.64 h60
  text "MANUFACTURER'S UL:" at 11407.23,-145.36 h60
  text "RAIL" at 12572.96,-149.65 h60
  text "METAL" at 13064.77,-149.65 h60
  text "X" at 13440,-150 h60
  text "SILK" at 13576.46,-149.65 h60
  text ".Layer_Name" at 577,-1958.49 h60
M11 Gerber Information:
  lines w10: -292,-2030.17 6308,-2030.17 ; -292,-1826.83 6310,-1826.83 ; -292,-1623.5 -292,-2233.5 3713,-2233.5 6310,-2233.5 6310,-1623.5 -291.5,-1623.5 -291.5,-2233.5 1284,-2233.5 ; 2173,-2233.5 2173,-1623.5 ; 3440,-1826.83 3440,-1623.5 ; 4280,-1826.83 4280,-1623.5 ; 4902,-2240 4902,-2037.17
  text "ALL ARTWORK VIEWED FROM TOP SIDE" at -228.5,-1755.67 h60
  text "BOARD #:" at 2248,-1755.67 h60
  text ".PRJ_Number" at 2793.5,-1755.67 h60
  text "REV:" at 3638,-1755.67 h60
  text ".PCB_Rev" at 3929.5,-1755.67 h60
  text "SVN REV:" at 4476,-1755.67 h60
  text ".VersionControl_RevNumber" at 4982,-1755.67 h60
  text "LAYER NAME =" at -228.5,-1958.49 h60
  text "PLOT NAME =" at -228.5,-2164.34 h60
  text ".plot_File_Name" at 577,-2164.34 h60
  text "GENERATED    :" at 2250,-2164.34 h60
  text ".Print_Date" at 3119.5,-2164.34 h60
  text ".Print_Time" at 3848.5,-2164.34 h60
  text "TEXAS INSTRUMENTS" at 5113,-2164.34 h60
M12 Stackup:
  drawing of 399 lines, arcs and shapes, not listed
  text "Layer" at 5875.93,6665 h60
  text "Name" at 6285.85,6665 h60
  text "Material" at 7815.4,6665 h60
  text "Thickness" at 8675.16,6665 h60
  text "Constant" at 9325,6665 h60
  text "Board Layer Stack" at 9894.86,6665 h60
  text "1" at 5875.93,6545 h60
  text "Top Overlay" at 6285.85,6545 h60
  text "2" at 5875.93,6425 h60
  text "Top Solder" at 6285.85,6425 h60
  text "Solder Resist" at 7815.4,6425 h60
  text "0.40mil" at 8675.16,6425 h60
  text "3.5" at 9325,6425 h60
  text "3" at 5875.93,6305 h60
  text "Layer 1 - Top Layer" at 6285.85,6305 h60
  text "Copper" at 7815.4,6305 h60
  text "1.40mil" at 8675.16,6305 h60
  text "4" at 5875.93,6185 h60
  text "Dielectric1" at 6285.85,6185 h60
  text "FR-4 High Tg" at 7815.4,6185 h60
  text "10.00mil" at 8675.16,6185 h60
  text "4.8" at 9325,6185 h60
  text "5" at 5875.93,6065 h60
  text "Layer 2 - Inner Signal 1" at 6285.85,6065 h60
  text "Copper" at 7815.4,6065 h60
  text "2.80mil" at 8675.16,6065 h60
  text "6" at 5875.93,5945 h60
  text "Dielectric2" at 6285.85,5945 h60
  text "FR-4 High Tg" at 7815.4,5945 h60
  text "10.00mil" at 8675.16,5945 h60
  text "4.8" at 9325,5945 h60
  text "7" at 5875.93,5825 h60
  text "Layer 3 - Inner Signal 2" at 6285.85,5825 h60
  text "Copper" at 7815.4,5825 h60
  text "2.80mil" at 8675.16,5825 h60
  text "8" at 5875.93,5705 h60
  text "Dielectric3" at 6285.85,5705 h60
  text "FR-4 High Tg" at 7815.4,5705 h60
  text "10.00mil" at 8675.16,5705 h60
  text "4.8" at 9325,5705 h60
  text "9" at 5875.93,5585 h60
  text "Layer 4 - Inner Signal 3" at 6285.85,5585 h60
  text "Copper" at 7815.4,5585 h60
  text "2.80mil" at 8675.16,5585 h60
  text "10" at 5875.93,5465 h60
  text "Dielectric4" at 6285.85,5465 h60
  text "FR-4 High Tg" at 7815.4,5465 h60
  text "10.00mil" at 8675.16,5465 h60
  text "4.8" at 9325,5465 h60
  text "11" at 5875.93,5345 h60
  text "Layer 5 - Inner Signal 4" at 6285.85,5345 h60
  text "Copper" at 7815.4,5345 h60
  text "2.80mil" at 8675.16,5345 h60
  text "12" at 5875.93,5225 h60
  text "Dielectric5" at 6285.85,5225 h60
  text "FR-4 High Tg" at 7815.4,5225 h60
  text "10.00mil" at 8675.16,5225 h60
  text "4.8" at 9325,5225 h60
  text "13" at 5875.93,5105 h60
  text "Layer 6 - Bottom Layer" at 6285.85,5105 h60
  text "Copper" at 7815.4,5105 h60
  text "1.40mil" at 8675.16,5105 h60
  text "14" at 5875.93,4985 h60
  text "Bottom Solder" at 6285.85,4985 h60
  text "Solder Resist" at 7815.4,4985 h60
  text "0.40mil" at 8675.16,4985 h60
  text "3.5" at 9325,4985 h60
  text "15" at 5875.93,4865 h60
  text "Bottom Overlay" at 6285.85,4865 h60
  text ".Layer_Name" at 577,-1958.49 h60
M13 Component Bodies Top:
  text ".Layer_Name" at 577,-1958.49 h60
M14 Component Bodies Bottom:
  text ".Layer_Name" at 577,-1958.49 h60
M15 Courtyards Top:
  text ".Layer_Name" at 577,-1958.49 h60
M16 Courtyards Bottom:
  text ".Layer_Name" at 577,-1958.49 h60
Drill Drawing:
  lines w12: 9106.55,1992.14 10995.66,1992.14 ; 9106.55,4383.08 10995.66,4383.08 ; 9422.19,1892.52 9422.19,4482.7 ; 9739.37,1892.52 9739.37,4482.7 ; 10361.11,1892.52 10361.11,4482.7 ; 10605.44,1892.52 10605.44,4482.7 ; 9106.55,1892.52 10995.66,1892.52 10995.66,4482.7 9106.55,4482.7 9106.55,1892.52
  text "Symbol" at 9166.33,4412.97 h72
  text "Quantity" at 9452.07,4412.97 h72
  text "Finished Hole Size" at 9769.26,4412.97 h72
  text "Plated" at 10391,4412.97 h72
  text "Hole Type" at 10635.32,4412.97 h72
  text "^" at 9144.7,4318.11 h44.28
  text "2" at 9452.07,4313.35 h60
  text "98.03mil (2.490mm)" at 9769.26,4313.35 h60
  text "NPTH" at 10391,4313.35 h60
  text "Round" at 10635.32,4313.35 h60
  text "2" at 9452.07,4213.72 h60
  text "137.80mil (3.500mm)" at 9769.26,4213.72 h60
  text "NPTH" at 10391,4213.72 h60
  text "Round" at 10635.32,4213.72 h60
  text "T" at 9144.7,4203.73 h44.28
  text "17" at 9452.07,4114.1 h60
  text "7.87mil (0.200mm)" at 9769.26,4114.1 h60
  text "PTH" at 10391,4114.1 h60
  text "Round" at 10635.32,4114.1 h60
  text "c" at 9144.7,4111.49 h44.28
  text "148" at 9452.07,4014.48 h60
  text "10.00mil (0.254mm)" at 9769.26,4014.48 h60
  text "PTH" at 10391,4014.48 h60
  text "Round" at 10635.32,4014.48 h60
  text "a" at 9144.7,4011.86 h44.28
  text "2" at 9452.07,3914.86 h60
  text "12.00mil (0.305mm)" at 9769.26,3914.86 h60
  text "PTH" at 10391,3914.86 h60
  text "Round" at 10635.32,3914.86 h60
  text "b" at 9144.7,3904.86 h44.28
  text "4" at 9452.07,3815.23 h60
  text "25.59mil (0.650mm)" at 9769.26,3815.23 h60
  text "PTH" at 10391,3815.23 h60
  text "Round" at 10635.32,3815.23 h60
  text "S" at 9144.7,3805.24 h44.28
  text "14" at 9452.07,3715.61 h60
  text "33.46mil (0.850mm)" at 9769.26,3715.61 h60
  text "PTH" at 10391,3715.61 h60
  text "Round" at 10635.32,3715.61 h60
  text "P" at 9144.7,3705.62 h44.28
  text "2" at 9452.07,3615.99 h60
  text "35.43mil (0.900mm)" at 9769.26,3615.99 h60
  text "PTH" at 10391,3615.99 h60
  text "Round" at 10635.32,3615.99 h60
  text "W" at 9144.7,3606 h44.28
  text "44" at 9452.07,3516.37 h60
  text "40.00mil (1.016mm)" at 9769.26,3516.37 h60
  text "PTH" at 10391,3516.37 h60
  text "Round" at 10635.32,3516.37 h60
  text "M" at 9144.7,3506.37 h44.28
  text "24" at 9452.07,3416.74 h60
  text "40.16mil (1.020mm)" at 9769.26,3416.74 h60
  text "PTH" at 10391,3416.74 h60
  text "Round" at 10635.32,3416.74 h60
  text "Z" at 9144.7,3406.75 h44.28
  text "7" at 9452.07,3317.12 h60
  text "41.34mil (1.050mm)" at 9769.26,3317.12 h60
  text "PTH" at 10391,3317.12 h60
  text "Round" at 10635.32,3317.12 h60
  text "Q" at 9144.7,3307.13 h44.28
  text "`" at 9152.07,3222.26 h44.28
  text "10" at 9452.07,3217.5 h60
  text "47.24mil (1.200mm)" at 9769.26,3217.5 h60
  text "PTH" at 10391,3217.5 h60
  text "Round" at 10635.32,3217.5 h60
  text "3" at 9452.07,3117.88 h60
  text "49.21mil (1.250mm)" at 9769.26,3117.88 h60
  text "PTH" at 10391,3117.88 h60
  text "Round" at 10635.32,3117.88 h60
  text "Y" at 9144.7,3107.88 h44.28
  text "8" at 9452.07,3018.26 h60
  text "50.00mil (1.270mm)" at 9769.26,3018.26 h60
  text "PTH" at 10391,3018.26 h60
  text "Round" at 10635.32,3018.26 h60
  text "O" at 9144.7,3008.26 h44.28
  text "4" at 9452.07,2918.63 h60
  text "51.18mil (1.300mm)" at 9769.26,2918.63 h60
  text "PTH" at 10391,2918.63 h60
  text "Round" at 10635.32,2918.63 h60
  text "[" at 9152.07,2908.64 h44.28
  text "32" at 9452.07,2819.01 h60
  text "51.97mil (1.320mm)" at 9769.26,2819.01 h60
  text "PTH" at 10391,2819.01 h60
  text "Round" at 10635.32,2819.01 h60
  text "]" at 9152.07,2809.02 h44.28
  text "_" at 9144.7,2731.53 h44.28
  text "2" at 9452.07,2719.39 h60
  text "55.12mil (1.400mm)" at 9769.26,2719.39 h60
  text "PTH" at 10391,2719.39 h60
  text "Round" at 10635.32,2719.39 h60
  text "4" at 9452.07,2619.77 h60
  text "59.06mil (1.500mm)" at 9769.26,2619.77 h60
  text "PTH" at 10391,2619.77 h60
  text "Round" at 10635.32,2619.77 h60
  text "X" at 9144.7,2609.77 h44.28
  text "6" at 9452.07,2520.14 h60
  text "62.00mil (1.575mm)" at 9769.26,2520.14 h60
  text "PTH" at 10391,2520.14 h60
  text "Round" at 10635.32,2520.14 h60
  text "R" at 9144.7,2510.15 h44.28
  text "4" at 9452.07,2420.52 h60
  text "63.50mil (1.613mm)" at 9769.26,2420.52 h60
  text "PTH" at 10391,2420.52 h60
  text "Round" at 10635.32,2420.52 h60
  text "E" at 9144.7,2410.53 h44.28
  text "3" at 9452.07,2320.9 h60
  text "70.00mil (1.778mm)" at 9769.26,2320.9 h60
  text "PTH" at 10391,2320.9 h60
  text "Round" at 10635.32,2320.9 h60
  text "U" at 9144.7,2310.91 h44.28
  text "4" at 9452.07,2221.28 h60
  text "72.83mil (1.850mm)" at 9769.26,2221.28 h60
  text "PTH" at 10391,2221.28 h60
  text "Round" at 10635.32,2221.28 h60
  text "\" at 9144.7,2218.66 h44.28
  text "5" at 9452.07,2121.65 h60
  text "75.00mil (1.905mm)" at 9769.26,2121.65 h60
  text "PTH" at 10391,2121.65 h60
  text "Round" at 10635.32,2121.65 h60
  text "H" at 9144.7,2111.66 h44.28
  text "6" at 9452.07,2022.03 h60
  text "125.98mil (3.200mm)" at 9769.26,2022.03 h60
  text "PTH" at 10391,2022.03 h60
  text "Round" at 10635.32,2022.03 h60
  text "N" at 9144.7,2012.04 h44.28
  text "357 Total" at 9452.07,1922.41 h60

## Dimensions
0,0 to 7700,0 on M2 Board Dimensions
0,0 to 0,3300 on M2 Board Dimensions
